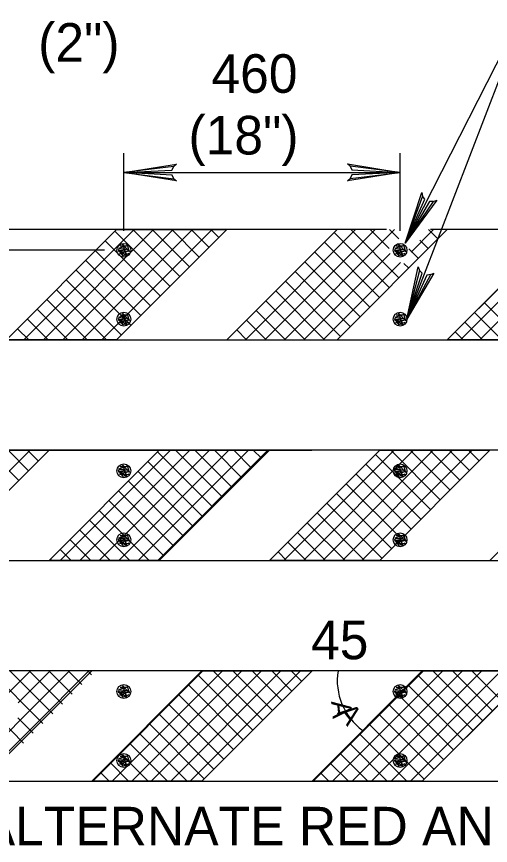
# Model space of a CAD drawing. Extents: x -4 to 901, y -468 to 720.
# Drawn here: x 138.7 to 180, y -23.4 to 48.7 of the extents above; entities that cross this region are included whole.
import ezdxf

# ---------------------------------------------------------------- set-up
doc = ezdxf.new("R2010")
doc.units = 0
doc.layers.add('2', color=7, linetype='Continuous')
doc.layers.add('3', color=7, linetype='Continuous')

msp = doc.modelspace()

# ---------------------------------------------------------------- linework, layer by layer
at = {"layer": '2'}
for p, q in [((148.05975, 30.043875), (148.05975, 36.817875)), ((172.12375, 30.043875), (172.12375, 36.817875)), ((148.05975, 35.137875), (172.12375, 35.137875)), ((137.83175, 20.563875), (147.43175, 30.163875)), ((147.43175, 20.563875), (157.03175, 30.163875)), ((157.03175, 20.563875), (166.63175, 30.163875)), ((166.63175, 20.563875), (176.23175, 30.163875)), ((176.23175, 20.563875), (185.83175, 30.163875)), ((148.30575, 27.877875), (147.96375, 28.861875)), ((147.96375, 28.861875), (148.56375, 28.219875)), ((172.36975, 27.877875), (172.02775, 28.861875)), ((172.02775, 28.861875), (172.62775, 28.219875)), ((146.37975, 28.363875), (133.87525, 28.363875)), ((148.44975, 28.453875), (147.56175, 28.285875)), ((147.98775, 27.877875), (147.56175, 28.423875)), ((147.56175, 28.423875), (148.30575, 27.877875)), ((147.56175, 28.285875), (148.55175, 28.321875)), ((148.29375, 28.735875), (147.60375, 28.501875)), ((147.60375, 28.501875), (148.44975, 28.453875)), ((148.55175, 28.321875), (147.66975, 28.051875)), ((147.72975, 28.735875), (148.29375, 28.735875)), ((148.05975, 28.363875), (148.05975, 28.363875)), ((148.56375, 28.219875), (148.38375, 28.801875)), ((172.51375, 28.453875), (171.62575, 28.285875)), ((172.05175, 27.877875), (171.62575, 28.423875)), ((171.62575, 28.423875), (172.36975, 27.877875)), ((171.62575, 28.285875), (172.61575, 28.321875)), ((172.35775, 28.735875), (171.66775, 28.501875)), ((171.66775, 28.501875), (172.51375, 28.453875)), ((172.61575, 28.321875), (171.73375, 28.051875)), ((171.79375, 28.735875), (172.35775, 28.735875)), ((172.12375, 28.363875), (172.12375, 28.363875)), ((172.62775, 28.219875), (172.44775, 28.801875)), ((147.66975, 28.051875), (148.48575, 28.069875)), ((148.48575, 28.069875), (147.98775, 27.877875)), ((171.73375, 28.051875), (172.54975, 28.069875)), ((172.54975, 28.069875), (172.05175, 27.877875)), ((148.44975, 22.453875), (147.56175, 22.285875)), ((147.98775, 21.877875), (147.56175, 22.423875)), ((147.56175, 22.423875), (148.30575, 21.877875)), ((148.29375, 22.735875), (147.60375, 22.501875)), ((147.60375, 22.501875), (148.44975, 22.453875)), ((147.72975, 22.735875), (148.29375, 22.735875)), ((148.30575, 21.877875), (147.96375, 22.861875)), ((147.96375, 22.861875), (148.56375, 22.219875)), ((148.05975, 22.363875), (148.05975, 22.363875)), ((148.56375, 22.219875), (148.38375, 22.801875)), ((172.51375, 22.453875), (171.62575, 22.285875)), ((172.05175, 21.877875), (171.62575, 22.423875)), ((171.62575, 22.423875), (172.36975, 21.877875)), ((172.35775, 22.735875), (171.66775, 22.501875)), ((171.66775, 22.501875), (172.51375, 22.453875)), ((171.79375, 22.735875), (172.35775, 22.735875)), ((172.36975, 21.877875), (172.02775, 22.861875)), ((172.02775, 22.861875), (172.62775, 22.219875)), ((172.12375, 22.363875), (172.12375, 22.363875)), ((172.62775, 22.219875), (172.44775, 22.801875)), ((147.56175, 22.285875), (148.55175, 22.321875)), ((148.55175, 22.321875), (147.66975, 22.051875)), ((147.66975, 22.051875), (148.48575, 22.069875)), ((148.48575, 22.069875), (147.98775, 21.877875)), ((171.62575, 22.285875), (172.61575, 22.321875)), ((172.61575, 22.321875), (171.73375, 22.051875)), ((171.73375, 22.051875), (172.54975, 22.069875)), ((172.54975, 22.069875), (172.05175, 21.877875)), ((243.5185, 10.963875), (111.99775, 10.963875)), ((113.43775, 10.963875), (164.43975, 10.963875)), ((113.43775, 10.963875), (164.43975, 10.963875)), ((131.94575, 1.363875), (141.54575, 10.963875)), ((131.94575, 1.363875), (141.54575, 10.963875)), ((141.54575, 1.363875), (151.14575, 10.963875)), ((141.54575, 1.363875), (151.14575, 10.963875)), ((151.14575, 1.363875), (160.74575, 10.963875)), ((151.14575, 1.363875), (160.74575, 10.963875)), ((160.74575, 1.363875), (170.34575, 10.963875)), ((160.74575, 1.363875), (170.34575, 10.963875)), ((170.34575, 1.363875), (179.94575, 10.963875)), ((170.34575, 1.363875), (179.94575, 10.963875)), ((179.94575, 1.363875), (189.54575, 10.963875)), ((179.94575, 1.363875), (189.54575, 10.963875)), ((148.29375, 9.535875), (147.60375, 9.301875)), ((147.72975, 9.535875), (148.29375, 9.535875)), ((148.30575, 8.677875), (147.96375, 9.661875)), ((147.96375, 9.661875), (148.56375, 9.019875)), ((148.56375, 9.019875), (148.38375, 9.601875)), ((172.35775, 9.535875), (171.66775, 9.301875)), ((171.79375, 9.535875), (172.35775, 9.535875)), ((172.36975, 8.677875), (172.02775, 9.661875)), ((172.02775, 9.661875), (172.62775, 9.019875)), ((172.62775, 9.019875), (172.44775, 9.601875)), ((148.44975, 9.253875), (147.56175, 9.085875)), ((147.98775, 8.677875), (147.56175, 9.223875)), ((147.56175, 9.223875), (148.30575, 8.677875)), ((147.56175, 9.085875), (148.55175, 9.121875)), ((147.60375, 9.301875), (148.44975, 9.253875)), ((148.55175, 9.121875), (147.66975, 8.851875)), ((147.66975, 8.851875), (148.48575, 8.869875)), ((148.48575, 8.869875), (147.98775, 8.677875)), ((148.05975, 9.163875), (148.05975, 9.163875)), ((148.05975, 9.163875), (148.05975, 9.163875)), ((172.51375, 9.253875), (171.62575, 9.085875)), ((172.05175, 8.677875), (171.62575, 9.223875)), ((171.62575, 9.223875), (172.36975, 8.677875)), ((171.62575, 9.085875), (172.61575, 9.121875)), ((171.66775, 9.301875), (172.51375, 9.253875)), ((172.61575, 9.121875), (171.73375, 8.851875)), ((171.73375, 8.851875), (172.54975, 8.869875)), ((172.54975, 8.869875), (172.05175, 8.677875)), ((172.12375, 9.163875), (172.12375, 9.163875)), ((172.12375, 9.163875), (172.12375, 9.163875)), ((161.76375, 2.381875), (166.16975, 6.787875)), ((161.76375, 2.381875), (166.16975, 6.787875)), ((148.30575, 2.677875), (147.96375, 3.661875)), ((147.96375, 3.661875), (148.56375, 3.019875)), ((172.36975, 2.677875), (172.02775, 3.661875)), ((172.02775, 3.661875), (172.62775, 3.019875)), ((148.44975, 3.253875), (147.56175, 3.085875)), ((147.98775, 2.677875), (147.56175, 3.223875)), ((147.56175, 3.223875), (148.30575, 2.677875)), ((147.56175, 3.085875), (148.55175, 3.121875)), ((148.29375, 3.535875), (147.60375, 3.301875)), ((147.60375, 3.301875), (148.44975, 3.253875)), ((148.55175, 3.121875), (147.66975, 2.851875)), ((147.72975, 3.535875), (148.29375, 3.535875)), ((148.05975, 3.163875), (148.05975, 3.163875)), ((148.05975, 3.163875), (148.05975, 3.163875)), ((148.56375, 3.019875), (148.38375, 3.601875)), ((172.51375, 3.253875), (171.62575, 3.085875)), ((172.05175, 2.677875), (171.62575, 3.223875)), ((171.62575, 3.223875), (172.36975, 2.677875)), ((171.62575, 3.085875), (172.61575, 3.121875)), ((172.35775, 3.535875), (171.66775, 3.301875)), ((171.66775, 3.301875), (172.51375, 3.253875)), ((172.61575, 3.121875), (171.73375, 2.851875)), ((171.79375, 3.535875), (172.35775, 3.535875)), ((172.12375, 3.163875), (172.12375, 3.163875)), ((172.12375, 3.163875), (172.12375, 3.163875)), ((172.62775, 3.019875), (172.44775, 3.601875)), ((147.66975, 2.851875), (148.48575, 2.869875)), ((148.48575, 2.869875), (147.98775, 2.677875)), ((171.73375, 2.851875), (172.54975, 2.869875)), ((172.54975, 2.869875), (172.05175, 2.677875)), ((111.99775, 1.363875), (243.5185, 1.363875)), ((243.5185, -8.236125), (111.99775, -8.236125)), ((135.65975, -17.836125), (145.25975, -8.236125)), ((135.65975, -17.836125), (145.25975, -8.236125)), ((145.25975, -17.836125), (154.85975, -8.236125)), ((145.25975, -17.836125), (154.85975, -8.236125)), ((154.85975, -17.836125), (164.45975, -8.236125)), ((154.85975, -17.836125), (164.45975, -8.236125)), ((164.45975, -17.836125), (174.05975, -8.236125)), ((164.45975, -17.836125), (174.05975, -8.236125)), ((174.05975, -17.836125), (183.65975, -8.236125)), ((174.05975, -17.836125), (183.65975, -8.236125)), ((148.44975, -9.946125), (147.56175, -10.114125)), ((147.98775, -10.522125), (147.56175, -9.976125)), ((147.56175, -9.976125), (148.30575, -10.522125)), ((147.56175, -10.114125), (148.55175, -10.078125)), ((148.29375, -9.664125), (147.60375, -9.898125)), ((147.60375, -9.898125), (148.44975, -9.946125)), ((148.55175, -10.078125), (147.66975, -10.348125)), ((147.72975, -9.664125), (148.29375, -9.664125)), ((148.30575, -10.522125), (147.96375, -9.538125)), ((147.96375, -9.538125), (148.56375, -10.180125)), ((148.05975, -10.036125), (148.05975, -10.036125)), ((148.05975, -10.036125), (148.05975, -10.036125)), ((148.56375, -10.180125), (148.38375, -9.598125)), ((172.51375, -9.946125), (171.62575, -10.114125)), ((172.05175, -10.522125), (171.62575, -9.976125)), ((171.62575, -9.976125), (172.36975, -10.522125)), ((171.62575, -10.114125), (172.61575, -10.078125)), ((172.35775, -9.664125), (171.66775, -9.898125)), ((171.66775, -9.898125), (172.51375, -9.946125)), ((172.61575, -10.078125), (171.73375, -10.348125)), ((171.79375, -9.664125), (172.35775, -9.664125)), ((172.36975, -10.522125), (172.02775, -9.538125)), ((172.02775, -9.538125), (172.62775, -10.180125)), ((172.12375, -10.036125), (172.12375, -10.036125)), ((172.12375, -10.036125), (172.12375, -10.036125)), ((172.62775, -10.180125), (172.44775, -9.598125)), ((147.66975, -10.348125), (148.48575, -10.330125)), ((148.48575, -10.330125), (147.98775, -10.522125)), ((171.73375, -10.348125), (172.54975, -10.330125)), ((172.54975, -10.330125), (172.05175, -10.522125)), ((148.29375, -15.664125), (147.60375, -15.898125)), ((147.72975, -15.664125), (148.29375, -15.664125)), ((148.30575, -16.522125), (147.96375, -15.538125)), ((147.96375, -15.538125), (148.56375, -16.180125)), ((148.56375, -16.180125), (148.38375, -15.598125)), ((172.35775, -15.664125), (171.66775, -15.898125)), ((171.79375, -15.664125), (172.35775, -15.664125)), ((172.36975, -16.522125), (172.02775, -15.538125)), ((172.02775, -15.538125), (172.62775, -16.180125)), ((172.62775, -16.180125), (172.44775, -15.598125)), ((148.44975, -15.946125), (147.56175, -16.114125)), ((147.98775, -16.522125), (147.56175, -15.976125)), ((147.56175, -15.976125), (148.30575, -16.522125)), ((147.56175, -16.114125), (148.55175, -16.078125)), ((147.60375, -15.898125), (148.44975, -15.946125)), ((148.55175, -16.078125), (147.66975, -16.348125)), ((147.66975, -16.348125), (148.48575, -16.330125)), ((148.48575, -16.330125), (147.98775, -16.522125)), ((148.05975, -16.036125), (148.05975, -16.036125)), ((148.05975, -16.036125), (148.05975, -16.036125)), ((172.51375, -15.946125), (171.62575, -16.114125)), ((172.05175, -16.522125), (171.62575, -15.976125)), ((171.62575, -15.976125), (172.36975, -16.522125)), ((171.62575, -16.114125), (172.61575, -16.078125)), ((171.66775, -15.898125), (172.51375, -15.946125)), ((172.61575, -16.078125), (171.73375, -16.348125)), ((171.73375, -16.348125), (172.54975, -16.330125)), ((172.54975, -16.330125), (172.05175, -16.522125)), ((172.12375, -16.036125), (172.12375, -16.036125)), ((172.12375, -16.036125), (172.12375, -16.036125)), ((111.99775, -17.836125), (243.5185, -17.836125))]:
    msp.add_line(p, q, dxfattribs=at)
for points in [[(188.42975, 50.693875), (183.62975, 50.693875), (172.57375, 28.971875)], [(183.62975, 50.693875), (172.72375, 22.369875)], [(152.41975, 34.589875), (152.25775, 34.905875), (148.05975, 35.137875), (152.41975, 34.589875), (152.64375, 34.399875), (148.05975, 35.137875), (152.25375, 35.345875), (152.40775, 35.657875), (148.05975, 35.137875), (152.64375, 35.865875), (152.40775, 35.657875)], [(167.76375, 35.685875), (167.92575, 35.369875), (172.12375, 35.137875), (167.76375, 35.685875), (167.54175, 35.875875), (172.12375, 35.137875), (167.92975, 34.929875), (167.77775, 34.617875), (172.12375, 35.137875), (167.54175, 34.409875), (167.77775, 34.617875)], [(175.03775, 32.607875), (174.68375, 32.607875), (172.57375, 28.971875), (175.03775, 32.607875), (175.30975, 32.721875), (172.57375, 28.971875), (174.29175, 32.803875), (174.08175, 33.081875), (172.57375, 28.971875), (174.00375, 33.385875), (174.08175, 33.081875)], [(170.943, 30.163875), (111.99775, 30.163875), (111.99775, 20.563875), (244.7635, 20.563875)], [(139.35175, 20.563875), (148.95175, 30.163875)], [(141.04975, 20.563875), (150.64975, 30.163875)], [(142.74575, 20.563875), (152.34575, 30.163875)], [(144.44375, 20.563875), (154.04375, 30.163875)], [(146.13975, 20.563875), (155.73975, 30.163875)], [(152.08775, 25.219875), (147.28775, 30.019875)], [(152.93575, 26.067875), (148.83975, 30.163875)], [(153.78375, 26.915875), (150.53775, 30.163875)], [(154.63375, 27.763875), (152.23375, 30.163875)], [(155.48175, 28.613875), (153.93175, 30.163875)], [(156.32975, 29.461875), (155.62775, 30.163875)], [(158.64575, 20.563875), (168.24575, 30.163875)], [(160.34375, 20.563875), (169.94175, 30.163875)], [(162.03975, 20.563875), (171.63975, 30.163875)], [(171.17775, 25.107875), (166.37775, 29.907875)], [(172.02575, 25.957875), (167.81975, 30.163875)], [(171.1755, 28.505125), (169.51775, 30.163875)], [(172.0225, 29.353125), (171.21375, 30.161875)], [(173.0765, 28.206625), (175.03375, 30.163875)], [(175.41975, 29.351875), (174.60775, 30.163875)], [(249.87225, 20.563875), (255.99775, 20.563875), (255.99775, 30.163875), (174.7745, 30.163875)], [(177.37375, 20.563875), (186.97375, 30.161875)], [(179.07175, 20.563875), (188.66975, 30.163875)], [(151.23975, 24.369875), (146.43975, 29.169875)], [(170.32775, 24.259875), (165.52775, 29.059875)], [(174.57175, 28.503875), (173.83675, 29.238875)], [(150.38975, 23.521875), (145.58975, 28.321875)], [(169.47975, 23.411875), (164.67975, 28.211875)], [(173.72175, 27.653875), (172.8905, 28.485125)], [(149.54175, 22.673875), (144.74175, 27.473875)], [(163.73775, 20.563875), (171.2645, 28.090625)], [(168.63175, 22.563875), (163.83175, 27.363875)], [(165.43375, 20.563875), (172.1605, 27.290625)], [(172.87375, 26.805875), (172.461, 27.218875)], [(174.79975, 26.239875), (174.44775, 26.201875), (172.72375, 22.369875), (174.79975, 26.239875), (175.05975, 26.379875), (172.72375, 22.369875), (174.03575, 26.355875), (173.79975, 26.611875), (172.72375, 22.369875), (173.68975, 26.907875), (173.79975, 26.611875)], [(148.69375, 21.823875), (143.89375, 26.623875)], [(167.78375, 21.713875), (162.98375, 26.513875)], [(147.84375, 20.975875), (143.04375, 25.775875)], [(166.93375, 20.865875), (162.13375, 25.665875)], [(146.56175, 20.563875), (142.19575, 24.927875)], [(165.53975, 20.563875), (161.28575, 24.817875)], [(144.86375, 20.563875), (141.34775, 24.079875)], [(163.84375, 20.563875), (160.43775, 23.969875)], [(143.16775, 20.563875), (140.49975, 23.229875)], [(162.14575, 20.563875), (159.58975, 23.119875)], [(182.69575, 20.563875), (179.46375, 23.795875)], [(141.46975, 20.563875), (139.64975, 22.381875)], [(180.99975, 20.563875), (178.61575, 22.947875)], [(160.44975, 20.563875), (158.73975, 22.271875)], [(179.30175, 20.563875), (177.76575, 22.097875)], [(139.77375, 20.563875), (138.80175, 21.533875)], [(158.75175, 20.563875), (157.89175, 21.423875)], [(177.60575, 20.563875), (176.91775, 21.249875)], [(157.05575, 20.563875), (157.04375, 20.575875)], [(130.30375, 1.363875), (139.90175, 10.963875)], [(138.90975, 8.325875), (136.27175, 10.961875)], [(139.75775, 9.175875), (137.96975, 10.963875)], [(140.60575, 10.023875), (139.66575, 10.963875)], [(141.45375, 10.871875), (141.36375, 10.963875)], [(142.52575, 1.363875), (152.12375, 10.963875)], [(144.22175, 1.363875), (153.82175, 10.963875)], [(145.91975, 1.363875), (155.51975, 10.963875)], [(147.61575, 1.363875), (157.21575, 10.963875)], [(149.31375, 1.363875), (158.91375, 10.963875)], [(151.00975, 1.363875), (160.60975, 10.963875)], [(156.64775, 6.863875), (152.54775, 10.963875)], [(157.49575, 7.713875), (154.24575, 10.963875)], [(158.34375, 8.561875), (155.94375, 10.963875)], [(159.19175, 9.409875), (157.63975, 10.963875)], [(160.04175, 10.257875), (159.33775, 10.963875)], [(162.00775, 1.363875), (171.60775, 10.963875)], [(163.70375, 1.363875), (173.30375, 10.963875)], [(165.40175, 1.363875), (175.00175, 10.963875)], [(167.09775, 1.363875), (176.69775, 10.963875)], [(168.79575, 1.363875), (178.39575, 10.963875)], [(175.62575, 6.643875), (171.30775, 10.963875)], [(176.47575, 7.493875), (173.00575, 10.963875)], [(177.32375, 8.341875), (174.70175, 10.963875)], [(178.17175, 9.189875), (176.39975, 10.963875)], [(179.01975, 10.037875), (178.09575, 10.963875)], [(179.86975, 10.887875), (179.79375, 10.963875)], [(155.79775, 6.015875), (150.99775, 10.815875)], [(174.77775, 5.795875), (169.97775, 10.595875)], [(154.94975, 5.167875), (150.14975, 9.967875)], [(173.92975, 4.947875), (169.12975, 9.747875)], [(154.10175, 4.319875), (149.30175, 9.119875)], [(173.08175, 4.097875), (168.28175, 8.897875)], [(153.25375, 3.469875), (148.45375, 8.269875)], [(172.23175, 3.249875), (167.43175, 8.049875)], [(152.40375, 2.621875), (147.60375, 7.421875)], [(151.55575, 1.773875), (146.75575, 6.573875)], [(171.38375, 2.401875), (166.58375, 7.201875)], [(170.53575, 1.553875), (165.73575, 6.353875)], [(150.26975, 1.363875), (145.90775, 5.725875)], [(169.02775, 1.363875), (164.88775, 5.503875)], [(148.57175, 1.363875), (145.05975, 4.875875)], [(167.33175, 1.363875), (164.03775, 4.655875)], [(146.87575, 1.363875), (144.20975, 4.027875)], [(165.63375, 1.363875), (163.18975, 3.807875)], [(145.17775, 1.363875), (143.36175, 3.179875)], [(163.93775, 1.363875), (162.34175, 2.959875)], [(143.48175, 1.363875), (142.51375, 2.329875)], [(141.78375, 1.363875), (141.66375, 1.481875)], [(162.23975, 1.363875), (161.49375, 2.109875)], [(133.72575, -17.836125), (143.32575, -8.236125)], [(135.42375, -17.836125), (145.02375, -8.236125)], [(141.01375, -12.820125), (136.42975, -8.236125)], [(137.99225, -10.175625), (139.93175, -8.236125)], [(141.86175, -11.972125), (138.12775, -8.236125)], [(138.85725, -11.008625), (141.62975, -8.236125)], [(142.71175, -11.124125), (139.82375, -8.236125)], [(143.55975, -10.276125), (141.52175, -8.236125)], [(144.40775, -9.426125), (143.21775, -8.236125)], [(145.25575, -8.578125), (144.91575, -8.236125)], [(145.35175, -17.836125), (154.95175, -8.236125)], [(147.04975, -17.836125), (156.64975, -8.236125)], [(148.74575, -17.836125), (158.34575, -8.236125)], [(150.44375, -17.836125), (160.04375, -8.236125)], [(152.13975, -17.836125), (161.73975, -8.236125)], [(153.83775, -17.836125), (163.43775, -8.236125)], [(159.30575, -13.390125), (154.50575, -8.590125)], [(160.15375, -12.542125), (155.84975, -8.236125)], [(161.00175, -11.694125), (157.54575, -8.236125)], [(161.85175, -10.844125), (159.24375, -8.236125)], [(162.69975, -9.996125), (160.93975, -8.236125)], [(163.54775, -9.148125), (162.63775, -8.236125)], [(164.39775, -8.300125), (164.33375, -8.236125)], [(164.55175, -17.836125), (174.15175, -8.236125)], [(166.24775, -17.836125), (175.84775, -8.236125)], [(167.94575, -17.836125), (177.54575, -8.236125)], [(169.64175, -17.836125), (179.24175, -8.236125)], [(171.33975, -17.836125), (180.93975, -8.236125)], [(173.03575, -17.836125), (182.63575, -8.236125)], [(178.47375, -13.422125), (173.67375, -8.622125)], [(179.32175, -12.574125), (174.98575, -8.236125)], [(180.17175, -11.726125), (176.68375, -8.236125)], [(181.01975, -10.876125), (178.37975, -8.236125)], [(158.45775, -14.238125), (153.65775, -9.440125)], [(177.62575, -14.270125), (172.82575, -9.470125)], [(157.60775, -15.088125), (152.80775, -10.288125)], [(176.77775, -15.120125), (171.97775, -10.320125)], [(156.75975, -15.936125), (151.95975, -11.136125)], [(175.92775, -15.968125), (171.12775, -11.168125)], [(155.91175, -16.784125), (151.11175, -11.984125)], [(175.07975, -16.816125), (170.27975, -12.016125)], [(139.31775, -14.518125), (137.1895, -12.389875)], [(140.16575, -13.670125), (138.816, -12.320375)], [(155.06375, -17.634125), (150.26375, -12.834125)], [(174.23175, -17.664125), (169.43175, -12.864125)], [(153.56975, -17.836125), (149.41375, -13.682125)], [(172.70575, -17.836125), (168.58375, -13.714125)], [(151.87175, -17.836125), (148.56575, -14.530125)], [(171.00975, -17.836125), (167.73375, -14.562125)], [(150.17575, -17.836125), (147.71775, -15.378125)], [(169.31175, -17.836125), (166.88575, -15.410125)], [(148.47775, -17.836125), (146.86975, -16.228125)], [(167.61575, -17.836125), (166.03775, -16.258125)], [(146.78175, -17.836125), (146.01975, -17.076125)], [(165.91775, -17.836125), (165.18975, -17.108125)]]:
    msp.add_lwpolyline(points, dxfattribs=at)
for points in [[(137.83175, 20.563875), (147.43175, 30.163875), (157.03175, 30.163875), (147.43175, 20.563875)], [(176.23175, 20.563875), (185.83175, 30.163875), (195.43175, 30.163875), (185.83175, 20.563875)], [(122.34575, 1.363875), (131.94575, 10.963875), (141.54575, 10.963875), (131.94575, 1.363875)], [(141.54575, 1.363875), (151.14575, 10.963875), (160.74575, 10.963875), (151.14575, 1.363875)], [(160.74575, 1.363875), (170.34575, 10.963875), (179.94575, 10.963875), (170.34575, 1.363875)], [(145.25975, -17.836125), (154.85975, -8.236125), (164.45975, -8.236125), (154.85975, -17.836125)], [(164.45975, -17.836125), (174.05975, -8.236125), (183.65975, -8.236125), (174.05975, -17.836125)]]:
    msp.add_lwpolyline(points, close=True, dxfattribs=at)
for centre in [(148.06053, 28.362972), (172.12341, 28.362972), (148.06053, 22.362972), (172.12341, 22.362972), (148.06053, 9.162972), (172.12341, 9.162972), (148.06053, 3.162972), (172.12341, 3.162972), (148.06053, -10.037028), (172.12341, -10.037028), (148.06053, -16.037028), (172.12341, -16.037028)]:
    msp.add_circle(centre, 0.6, dxfattribs=at)
msp.add_arc((172.039012, -9.073735), 5.390059, 171.06977778, 233.93211667, dxfattribs=at)
msp.add_arc((172.039012, -9.073735), 5.390059, 171.06977778, 233.93211667, dxfattribs=at)

# ---------------------------------------------------------------- texts
for height, rotation, p in [(1.727796, 275.64735556, (166.10975, -10.900125)), (1.727796, 275.64735556, (166.10975, -10.900125)), (1.727688, 307.48319722, (166.60175, -11.900125)), (1.727688, 307.48319722, (166.60175, -11.900125))]:
    msp.add_text('A', height=height, rotation=rotation, dxfattribs=at).set_placement(p)
at = {"layer": '3'}
for s, height, p in [('(2")', 3.36, (140.59825, 44.771625)), ('460', 3.36, (155.69, 42.062375)), ('(18")', 3.36, (153.69025, 36.699125)), ('45', 3.359988, (164.36575, -7.226125)), ('ALTERNATE RED AND WHITE', 3.359988, (135.59175, -23.430125))]:
    msp.add_text(s, height=height, dxfattribs=at).set_placement(p)

doc.saveas('drawing.dxf')
